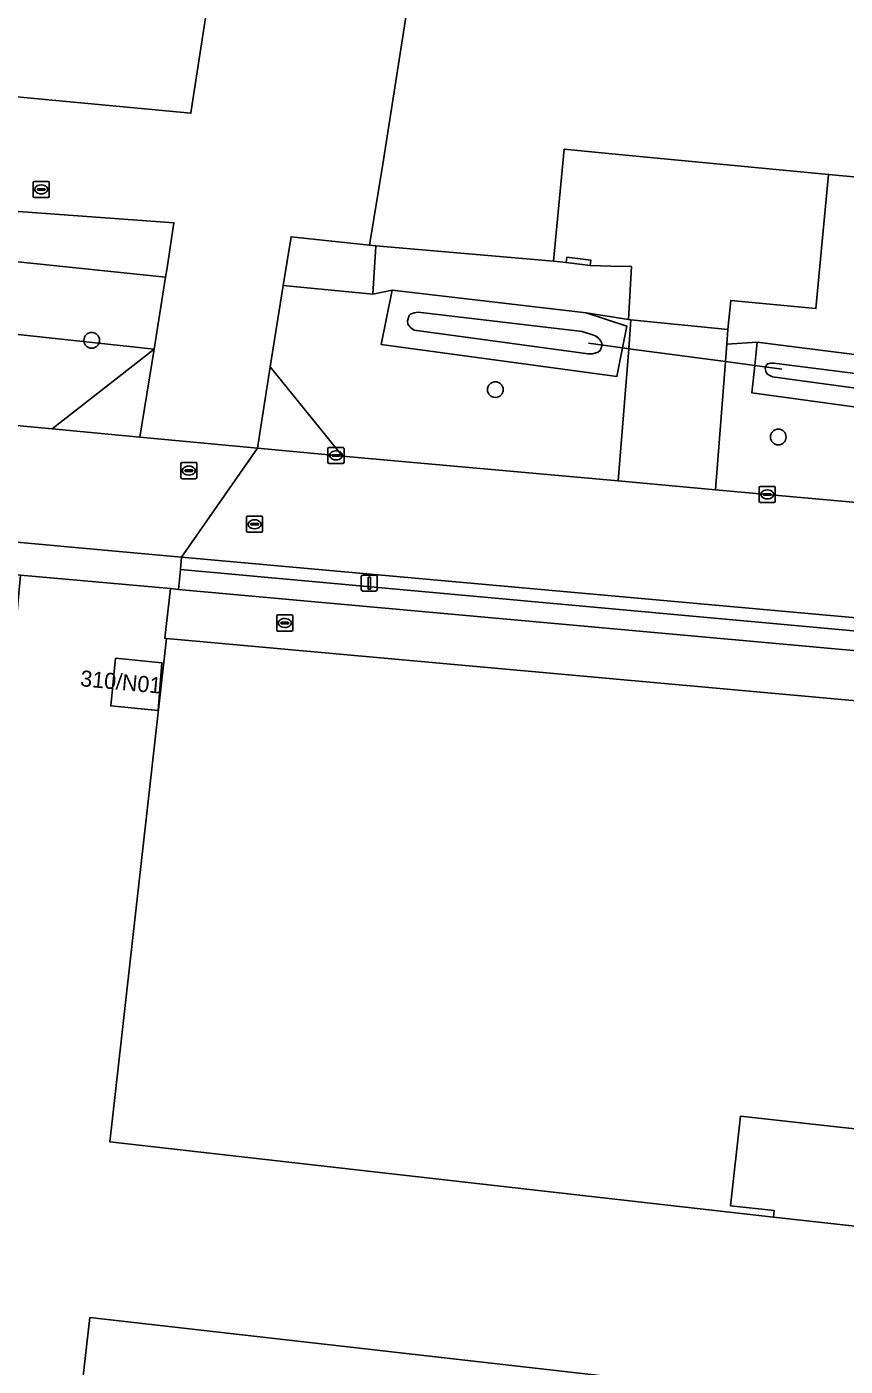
# Model space of a CAD drawing. Extents: x 161385 to 162589, y 388479 to 389756.
# Drawn here: x 162279.1 to 162330.1, y 388809.1 to 388892.6 of the extents above; entities that cross this region are included whole.
import ezdxf

# ---------------------------------------------------------------- set-up
doc = ezdxf.new("R2010")
doc.units = 0
for name, color, linetype in [('IMGEO_Berm_groen', 7, 'Continuous'), ('IMGEO_Boom', 7, 'Continuous'), ('IMGEO_Duiker', 7, 'Continuous'), ('IMGEO_Erf', 7, 'Continuous'), ('IMGEO_Groenvoorziening', 7, 'Continuous'), ('IMGEO_Haag', 7, 'Continuous'), ('IMGEO_Kolk', 7, 'Continuous'), ('IMGEO_Lichtmast', 7, 'Continuous'), ('IMGEO_Oever', 7, 'Continuous'), ('IMGEO_Pand', 7, 'Continuous'), ('IMGEO_Pand_nummerreeks', 7, 'Continuous'), ('IMGEO_Pand_overbouw', 7, 'Continuous'), ('IMGEO_Parkeervlak_open', 7, 'Continuous'), ('IMGEO_Rijbaan_lokaal_gesloten', 7, 'Continuous'), ('IMGEO_Rioolput', 7, 'Continuous'), ('IMGEO_Voetpad_open', 7, 'Continuous'), ('IMGEO_Waterloop', 7, 'Continuous')]:
    doc.layers.add(name, color=color, linetype=linetype)

msp = doc.modelspace()

# ---------------------------------------------------------------- linework, layer by layer
at = {"layer": 'IMGEO_Berm_groen'}
msp.add_lwpolyline([(162288.732, 388859.544), (162288.662, 388858.772), (162339.281, 388854.162), (162339.344, 388854.997)], close=True, dxfattribs=at)
at = {"layer": 'IMGEO_Boom'}
for centre in [(162283.136, 388873.045), (162308.29, 388869.973), (162325.926, 388867.021)]:
    msp.add_circle(centre, 0.489, dxfattribs=at)
at = {"layer": 'IMGEO_Duiker'}
msp.add_lwpolyline([(162314.103, 388872.857), (162316.222, 388872.573), (162316.604, 388872.522), (162322.632, 388871.715), (162324.463, 388871.47), (162326.14, 388871.245)], dxfattribs=at)
at = {"layer": 'IMGEO_Erf'}
for points in [[(162301.186, 388963.969), (162289.317, 388887.215), (162289.314, 388887.191), (162277.129, 388888.332), (162269.619, 388894.999)], [(162260.733, 388892.727), (162265.464, 388888.449), (162265.979, 388889.025), (162274.193, 388881.455), (162274.374, 388883.406), (162276.174, 388883.247), (162275.984, 388881.265), (162288.259, 388880.37), (162287.835, 388877.552), (162287.741, 388876.97), (162287.02, 388872.502), (162286.134, 388867.013), (162293.465, 388866.329), (162294.266, 388871.396), (162295.067, 388876.463), (162295.565, 388879.495), (162300.445, 388878.969), (162301.281, 388884.015), (162311.401, 388948.624)], [(162336.306, 388823.293), (162323.575, 388824.702), (162322.952, 388819.118), (162325.666, 388818.823), (162325.623, 388818.422), (162284.27, 388823.103), (162287.807, 388854.476), (162287.687, 388854.487), (162288.036, 388857.574), (162278.689, 388858.42), (162278.404, 388855.258), (162275.28, 388820.598), (162223.371, 388826.41), (162220.139, 388826.772), (162222.783, 388816.053), (162224.711, 388808.14)], [(162331.623, 388785.008), (162280.589, 388790.807), (162283.02, 388812.167), (162334.332, 388806.326)]]:
    msp.add_lwpolyline(points, dxfattribs=at)
msp.add_lwpolyline([(162287.271, 388849.977), (162284.326, 388850.264), (162284.615, 388853.236), (162287.513, 388852.954)], close=True, dxfattribs=at)
at = {"layer": 'IMGEO_Groenvoorziening'}
for points in [[(162246.366, 388906.419), (162244.168, 388904.202), (162253.513, 388895.632), (162268.907, 388882.41), (162271.544, 388879.695), (162274.103, 388878.687), (162276.507, 388878.144), (162287.741, 388876.97), (162287.835, 388877.552), (162288.259, 388880.37), (162275.984, 388881.265), (162274.193, 388881.455), (162265.979, 388889.025), (162265.464, 388888.449), (162260.733, 388892.727), (162261.179, 388893.207)], [(162244.168, 388904.202), (162245.865, 388891.335), (162245.122, 388884.323), (162255.956, 388878.959), (162267.356, 388874.616), (162287.02, 388872.502), (162287.741, 388876.97), (162276.507, 388878.144), (162274.103, 388878.687), (162271.544, 388879.695), (162268.907, 388882.41), (162253.513, 388895.632)], [(162255.956, 388878.959), (162245.122, 388884.323), (162242.339, 388884.577), (162241.028, 388871.088), (162277.557, 388867.813), (162280.677, 388867.522), (162287.02, 388872.502), (162267.356, 388874.616)], [(162300.445, 388878.969), (162295.565, 388879.495), (162295.067, 388876.463), (162300.649, 388875.922), (162300.833, 388878.935)], [(162316.778, 388877.634), (162315.492, 388877.672), (162314.206, 388877.71), (162312.713, 388877.887), (162311.923, 388877.971), (162300.833, 388878.935), (162300.649, 388875.922), (162301.863, 388876.172), (162313.948, 388874.754), (162316.588, 388874.337)], [(162316.604, 388872.522), (162316.746, 388874.312), (162316.588, 388874.337), (162313.948, 388874.754), (162316.487, 388873.93), (162316.222, 388872.573), (162315.873, 388870.781), (162301.185, 388872.774), (162301.863, 388876.172), (162300.649, 388875.922), (162295.067, 388876.463), (162294.266, 388871.396), (162298.769, 388865.835), (162315.95, 388864.281)]]:
    msp.add_lwpolyline(points, close=True, dxfattribs=at)
for points in [[(162357.822, 388901.413), (162352.295, 388877.281), (162351.615, 388874.313), (162351.606, 388874.213), (162348.394, 388874.517), (162334.421, 388875.837), (162335.09, 388882.809), (162329.062, 388883.383), (162328.267, 388875.021), (162322.959, 388875.526), (162322.786, 388873.71), (162322.717, 388872.815), (162324.614, 388872.923), (162339.222, 388871.074), (162341.408, 388871.373), (162344.443, 388871.418)], [(162344.503, 388866.742), (162340.703, 388867.092), (162339.127, 388867.743), (162324.286, 388869.767), (162324.463, 388871.47), (162324.614, 388872.923), (162322.717, 388872.815), (162322.632, 388871.715), (162322.016, 388863.733), (162325.24, 388863.441), (162339.626, 388862.148), (162340.13, 388862.129), (162341.25, 388862.022), (162342.375, 388862.016), (162343.496, 388862.11), (162344.605, 388862.304), (162345.691, 388862.596), (162346.747, 388862.984), (162345.812, 388867.043)], [(162339.12, 388852.95), (162288.552, 388857.528), (162288.036, 388857.574), (162287.687, 388854.487), (162287.807, 388854.476), (162339.069, 388849.833)]]:
    msp.add_lwpolyline(points, dxfattribs=at)
at = {"layer": 'IMGEO_Haag'}
msp.add_lwpolyline([(162300.445, 388878.969), (162295.565, 388879.495), (162295.067, 388876.463), (162300.649, 388875.922), (162300.833, 388878.935)], close=True, dxfattribs=at)
at = {"layer": 'IMGEO_Kolk'}
for p, q in [((162297.859, 388865.447), (162297.859, 388866.299)), ((162297.934, 388866.373), (162298.786, 388866.373)), ((162298.118, 388865.867), (162298.118, 388865.879)), ((162298.556, 388865.83), (162298.158, 388865.83)), ((162298.161, 388865.916), (162298.559, 388865.916)), ((162298.347, 388866.153), (162298.372, 388866.153)), ((162298.602, 388865.879), (162298.602, 388865.867)), ((162298.86, 388866.299), (162298.86, 388865.447)), ((162298.786, 388865.373), (162297.934, 388865.373)), ((162298.37, 388865.593), (162298.345, 388865.593)), ((162324.739, 388863.017), (162324.739, 388863.869)), ((162324.814, 388863.943), (162325.666, 388863.943)), ((162324.998, 388863.437), (162324.998, 388863.449)), ((162325.436, 388863.4), (162325.038, 388863.4)), ((162325.041, 388863.486), (162325.439, 388863.486)), ((162325.227, 388863.723), (162325.252, 388863.723)), ((162325.482, 388863.449), (162325.482, 388863.437)), ((162325.74, 388863.869), (162325.74, 388863.017)), ((162325.666, 388862.943), (162324.814, 388862.943)), ((162325.25, 388863.163), (162325.225, 388863.163))]:
    msp.add_line(p, q, dxfattribs=at)
for points in [[(162297.859, 388865.447), (162297.859, 388866.299)], [(162297.934, 388866.373), (162298.786, 388866.373)], [(162298.86, 388866.299), (162298.86, 388865.447)], [(162298.786, 388865.373), (162297.934, 388865.373)], [(162324.739, 388863.017), (162324.739, 388863.869)], [(162324.814, 388863.943), (162325.666, 388863.943)], [(162325.74, 388863.869), (162325.74, 388863.017)], [(162325.666, 388862.943), (162324.814, 388862.943)]]:
    msp.add_lwpolyline(points, dxfattribs=at)
for centre, radius, start, end in [((162297.936, 388866.297), 0.0765, 91.55205, 178.44795), ((162297.936, 388866.297), 0.0765, 91.55205, 178.44795), ((162298.158, 388865.876), 0.0403, 85.87752, 175.75265), ((162298.155, 388865.866), 0.0366, 178.93798, 274.71019), ((162298.559, 388865.873), 0.043, 264.86636, 352.45326), ((162298.563, 388865.878), 0.0386, 1.73085, 96.63898), ((162298.784, 388866.297), 0.0765, 1.55205, 88.44795), ((162298.784, 388866.297), 0.0765, 1.55205, 88.44795), ((162297.936, 388865.449), 0.0765, 181.55205, 268.44795), ((162297.936, 388865.449), 0.0765, 181.55205, 268.44795), ((162298.784, 388865.449), 0.0765, 271.55205, 358.44795), ((162298.784, 388865.449), 0.0765, 271.55205, 358.44795), ((162324.816, 388863.867), 0.0765, 91.55205, 178.44795), ((162324.816, 388863.867), 0.0765, 91.55205, 178.44795), ((162325.038, 388863.446), 0.0403, 85.87752, 175.75265), ((162325.035, 388863.436), 0.0366, 178.93798, 274.71019), ((162325.439, 388863.443), 0.043, 264.86636, 352.45326), ((162325.443, 388863.448), 0.0386, 1.73085, 96.63898), ((162325.664, 388863.867), 0.0765, 1.55205, 88.44795), ((162325.664, 388863.867), 0.0765, 1.55205, 88.44795), ((162324.816, 388863.019), 0.0765, 181.55205, 268.44795), ((162324.816, 388863.019), 0.0765, 181.55205, 268.44795), ((162325.664, 388863.019), 0.0765, 271.55205, 358.44795), ((162325.664, 388863.019), 0.0765, 271.55205, 358.44795)]:
    msp.add_arc(centre, radius, start, end, dxfattribs=at)
for centre, major_axis, ratio, start_param, end_param in [((162298.346, 388865.873), (-0.387, 0.002), 0.722429, 4.712389, 7.853982), ((162298.371, 388865.873), (-0.39, 0.002), 0.717154, 1.570796, 4.712389), ((162325.226, 388863.443), (-0.387, 0.002), 0.722429, 4.712389, 7.853982), ((162325.251, 388863.443), (-0.39, 0.002), 0.717154, 1.570796, 4.712389)]:
    msp.add_ellipse(centre, major_axis=major_axis, ratio=ratio, start_param=start_param, end_param=end_param, dxfattribs=at)
at = {"layer": 'IMGEO_Lichtmast'}
for p, q in [((162299.936, 388857.522), (162299.936, 388858.322)), ((162299.936, 388858.322), (162299.936, 388857.522)), ((162300.036, 388858.422), (162300.826, 388858.422)), ((162300.826, 388858.422), (162300.036, 388858.422)), ((162300.926, 388858.322), (162300.926, 388857.522)), ((162300.926, 388857.522), (162300.926, 388858.322)), ((162300.826, 388857.422), (162300.036, 388857.422)), ((162300.036, 388857.422), (162300.826, 388857.422))]:
    msp.add_line(p, q, dxfattribs=at)
msp.add_lwpolyline([(162300.356, 388858.297), (162300.506, 388858.297), (162300.506, 388857.547), (162300.356, 388857.547), (162300.356, 388858.297)], dxfattribs=at)
for centre, start, end in [((162300.036, 388858.322), 90, 180), ((162300.036, 388858.322), 90, 180), ((162300.826, 388858.322), 0, 90), ((162300.826, 388858.322), 360, 90), ((162300.036, 388857.522), 180, 270), ((162300.036, 388857.522), 180, 270), ((162300.826, 388857.522), 270, 0), ((162300.826, 388857.522), 270, 0)]:
    msp.add_arc(centre, 0.1, start, end, dxfattribs=at)
at = {"layer": 'IMGEO_Oever'}
for points in [[(162316.487, 388873.93), (162313.948, 388874.754), (162301.863, 388876.172), (162301.185, 388872.774), (162315.873, 388870.781), (162316.222, 388872.573)], [(162303.226, 388873.679), (162303.021, 388873.826), (162302.846, 388874.053), (162302.809, 388874.249), (162302.919, 388874.601), (162303.005, 388874.677), (162303.228, 388874.763), (162303.49, 388874.802), (162313.697, 388873.604), (162314.534, 388873.332), (162314.757, 388873.135), (162314.913, 388872.92), (162314.944, 388872.744), (162314.822, 388872.414), (162314.705, 388872.298), (162314.353, 388872.197), (162314.068, 388872.208)]]:
    msp.add_lwpolyline(points, close=True, dxfattribs=at)
for points in [[(162344.443, 388871.418), (162341.408, 388871.373), (162339.222, 388871.074), (162324.614, 388872.923), (162324.463, 388871.47), (162324.286, 388869.767), (162339.127, 388867.743), (162340.703, 388867.092), (162344.503, 388866.742)], [(162325.561, 388870.768), (162325.389, 388870.843), (162325.243, 388870.943), (162325.175, 388871.03), (162325.117, 388871.285), (162325.192, 388871.512), (162325.275, 388871.574), (162325.447, 388871.614), (162325.649, 388871.618), (162339.228, 388869.9), (162341.496, 388870.21), (162344.685, 388870.255)], [(162344.776, 388867.889), (162344.6, 388867.902), (162340.985, 388868.235), (162339.433, 388868.876), (162325.561, 388870.768)]]:
    msp.add_lwpolyline(points, dxfattribs=at)
at = {"layer": 'IMGEO_Pand'}
for points in [[(162264.946, 388889.847), (162268.212, 388893.373), (162269.619, 388894.999), (162277.129, 388888.332), (162289.314, 388887.191), (162289.317, 388887.215), (162301.186, 388963.969), (162272.023, 388970.049), (162248.708, 388913.782), (162251.019, 388911.636), (162246.366, 388906.419), (162261.179, 388893.207)], [(162329.062, 388883.383), (162335.09, 388882.809), (162334.421, 388875.837), (162348.394, 388874.517), (162351.606, 388874.213), (162351.615, 388874.313), (162352.295, 388877.281), (162357.822, 388901.413), (162350.993, 388902.975), (162351.799, 388906.466), (162359.012, 388937.762), (162358.244, 388937.938), (162354.138, 388938.878), (162348.019, 388940.254), (162347.32, 388937.213), (162321.535, 388943.142), (162322.217, 388946.171), (162311.401, 388948.624), (162301.281, 388884.015), (162300.445, 388878.969), (162300.833, 388878.935), (162311.923, 388877.971), (162312.587, 388884.951), (162316.198, 388884.607)], [(162312.713, 388877.887), (162314.206, 388877.71), (162314.244, 388878.037), (162312.752, 388878.215)], [(162287.513, 388852.954), (162284.615, 388853.236), (162284.326, 388850.264), (162287.271, 388849.977)], [(162334.332, 388806.326), (162283.02, 388812.167), (162280.589, 388790.807), (162331.623, 388785.008), (162331.535, 388784.179), (162331.85, 388784.151), (162332.058, 388785.932), (162334.379, 388785.658), (162334.24, 388784.715), (162338.936, 388784.171), (162340.623, 388800.353), (162340.638, 388800.493), (162333.756, 388801.193), (162334.321, 388806.194)]]:
    msp.add_lwpolyline(points, close=True, dxfattribs=at)
msp.add_lwpolyline([(162339.069, 388849.833), (162287.807, 388854.476), (162284.27, 388823.103), (162325.623, 388818.422), (162325.666, 388818.823), (162322.952, 388819.118), (162323.575, 388824.702), (162336.306, 388823.293), (162336.398, 388824.261), (162341.857, 388823.664), (162342.013, 388824.299), (162342.869, 388824.995), (162343.228, 388825.075), (162343.546, 388825.042), (162343.766, 388826.99), (162345.439, 388841.767)], dxfattribs=at)
at = {"layer": 'IMGEO_Pand_overbouw'}
msp.add_lwpolyline([(162336.306, 388823.293), (162323.575, 388824.702), (162322.952, 388819.118), (162325.666, 388818.823), (162325.623, 388818.422), (162335.604, 388817.317)], close=True, dxfattribs=at)
at = {"layer": 'IMGEO_Parkeervlak_open'}
msp.add_lwpolyline([(162316.588, 388874.337), (162316.746, 388874.312), (162322.786, 388873.71), (162322.959, 388875.526), (162328.267, 388875.021), (162329.062, 388883.383), (162316.198, 388884.607), (162312.587, 388884.951), (162311.923, 388877.971), (162312.713, 388877.887), (162312.752, 388878.215), (162314.244, 388878.037), (162314.206, 388877.71), (162315.492, 388877.672), (162316.778, 388877.634)], close=True, dxfattribs=at)
at = {"layer": 'IMGEO_Rijbaan_lokaal_gesloten'}
for points in [[(162224.271, 388865.333), (162239.911, 388863.928), (162253.792, 388862.682), (162273.651, 388860.898), (162288.732, 388859.544), (162293.465, 388866.329), (162286.134, 388867.013), (162280.677, 388867.522), (162277.557, 388867.813), (162241.028, 388871.088), (162237.058, 388871.444), (162235.953, 388871.543), (162215.116, 388873.448)], [(162339.626, 388862.148), (162325.24, 388863.441), (162322.016, 388863.733), (162315.95, 388864.281), (162298.769, 388865.835), (162298.36, 388865.872), (162293.465, 388866.329), (162288.732, 388859.544), (162339.344, 388854.997)]]:
    msp.add_lwpolyline(points, dxfattribs=at)
at = {"layer": 'IMGEO_Rioolput'}
for p, q in [((162279.489, 388882.022), (162279.489, 388882.874)), ((162279.564, 388882.948), (162280.416, 388882.948)), ((162279.748, 388882.442), (162279.748, 388882.454)), ((162280.186, 388882.405), (162279.788, 388882.405)), ((162279.791, 388882.491), (162280.189, 388882.491)), ((162279.977, 388882.728), (162280.002, 388882.728)), ((162280.232, 388882.454), (162280.232, 388882.442)), ((162280.49, 388882.874), (162280.49, 388882.022)), ((162280.416, 388881.948), (162279.564, 388881.948)), ((162280, 388882.168), (162279.975, 388882.168)), ((162288.69, 388864.499), (162288.69, 388865.351)), ((162288.765, 388865.425), (162289.617, 388865.425)), ((162288.949, 388864.919), (162288.949, 388864.931)), ((162289.387, 388864.882), (162288.989, 388864.882)), ((162288.992, 388864.968), (162289.39, 388864.968)), ((162289.178, 388865.205), (162289.203, 388865.205)), ((162289.433, 388864.931), (162289.433, 388864.919)), ((162289.691, 388865.351), (162289.691, 388864.499)), ((162289.617, 388864.425), (162288.765, 388864.425)), ((162289.201, 388864.645), (162289.176, 388864.645)), ((162292.787, 388861.16), (162292.787, 388862.012)), ((162292.862, 388862.086), (162293.714, 388862.086)), ((162293.046, 388861.58), (162293.046, 388861.592)), ((162293.484, 388861.543), (162293.086, 388861.543)), ((162293.089, 388861.629), (162293.487, 388861.629)), ((162293.275, 388861.866), (162293.3, 388861.866)), ((162293.53, 388861.592), (162293.53, 388861.58)), ((162293.788, 388862.012), (162293.788, 388861.16)), ((162293.714, 388861.086), (162292.862, 388861.086)), ((162293.298, 388861.306), (162293.273, 388861.306)), ((162294.67, 388855.007), (162294.67, 388855.859)), ((162294.745, 388855.933), (162295.597, 388855.933)), ((162295.158, 388855.713), (162295.183, 388855.713)), ((162295.671, 388855.859), (162295.671, 388855.007)), ((162295.597, 388854.933), (162294.745, 388854.933)), ((162294.929, 388855.427), (162294.929, 388855.439)), ((162295.367, 388855.39), (162294.969, 388855.39)), ((162294.972, 388855.476), (162295.37, 388855.476)), ((162295.181, 388855.153), (162295.156, 388855.153)), ((162295.413, 388855.439), (162295.413, 388855.427))]:
    msp.add_line(p, q, dxfattribs=at)
for points in [[(162279.489, 388882.022), (162279.489, 388882.874)], [(162279.564, 388882.948), (162280.416, 388882.948)], [(162280.49, 388882.874), (162280.49, 388882.022)], [(162280.416, 388881.948), (162279.564, 388881.948)], [(162288.69, 388864.499), (162288.69, 388865.351)], [(162288.765, 388865.425), (162289.617, 388865.425)], [(162289.691, 388865.351), (162289.691, 388864.499)], [(162289.617, 388864.425), (162288.765, 388864.425)], [(162292.787, 388861.16), (162292.787, 388862.012)], [(162292.862, 388862.086), (162293.714, 388862.086)], [(162293.788, 388862.012), (162293.788, 388861.16)], [(162293.714, 388861.086), (162292.862, 388861.086)], [(162294.67, 388855.007), (162294.67, 388855.859)], [(162294.745, 388855.933), (162295.597, 388855.933)], [(162295.671, 388855.859), (162295.671, 388855.007)], [(162295.597, 388854.933), (162294.745, 388854.933)]]:
    msp.add_lwpolyline(points, dxfattribs=at)
for centre, radius, start, end in [((162279.566, 388882.872), 0.0765, 91.55205, 178.44795), ((162279.566, 388882.872), 0.0765, 91.55205, 178.44795), ((162279.788, 388882.451), 0.0403, 85.87752, 175.75265), ((162279.785, 388882.441), 0.0366, 178.93798, 274.71019), ((162280.189, 388882.448), 0.043, 264.86636, 352.45326), ((162280.193, 388882.453), 0.0386, 1.73085, 96.63898), ((162280.414, 388882.872), 0.0765, 1.55205, 88.44795), ((162280.414, 388882.872), 0.0765, 1.55205, 88.44795), ((162279.566, 388882.024), 0.0765, 181.55205, 268.44795), ((162279.566, 388882.024), 0.0765, 181.55205, 268.44795), ((162280.414, 388882.024), 0.0765, 271.55205, 358.44795), ((162280.414, 388882.024), 0.0765, 271.55205, 358.44795), ((162288.767, 388865.349), 0.0765, 91.55205, 178.44795), ((162288.767, 388865.349), 0.0765, 91.55205, 178.44795), ((162288.989, 388864.928), 0.0403, 85.87752, 175.75265), ((162288.986, 388864.918), 0.0366, 178.93798, 274.71019), ((162289.39, 388864.925), 0.043, 264.86636, 352.45326), ((162289.394, 388864.93), 0.0386, 1.73085, 96.63898), ((162289.615, 388865.349), 0.0765, 1.55205, 88.44795), ((162289.615, 388865.349), 0.0765, 1.55205, 88.44795), ((162288.767, 388864.501), 0.0765, 181.55205, 268.44795), ((162288.767, 388864.501), 0.0765, 181.55205, 268.44795), ((162289.615, 388864.501), 0.0765, 271.55205, 358.44795), ((162289.615, 388864.501), 0.0765, 271.55205, 358.44795), ((162292.864, 388862.01), 0.0765, 91.55205, 178.44795), ((162292.864, 388862.01), 0.0765, 91.55205, 178.44795), ((162293.086, 388861.589), 0.0403, 85.87752, 175.75265), ((162293.083, 388861.579), 0.0366, 178.93798, 274.71019), ((162293.487, 388861.586), 0.043, 264.86636, 352.45326), ((162293.491, 388861.591), 0.0386, 1.73085, 96.63898), ((162293.712, 388862.01), 0.0765, 1.55205, 88.44795), ((162293.712, 388862.01), 0.0765, 1.55205, 88.44795), ((162292.864, 388861.162), 0.0765, 181.55205, 268.44795), ((162292.864, 388861.162), 0.0765, 181.55205, 268.44795), ((162293.712, 388861.162), 0.0765, 271.55205, 358.44795), ((162293.712, 388861.162), 0.0765, 271.55205, 358.44795), ((162294.747, 388855.857), 0.0765, 91.55205, 178.44795), ((162294.747, 388855.857), 0.0765, 91.55205, 178.44795), ((162295.595, 388855.857), 0.0765, 1.55205, 88.44795), ((162295.595, 388855.857), 0.0765, 1.55205, 88.44795), ((162294.747, 388855.009), 0.0765, 181.55205, 268.44795), ((162294.747, 388855.009), 0.0765, 181.55205, 268.44795), ((162294.969, 388855.436), 0.0403, 85.87752, 175.75265), ((162294.966, 388855.426), 0.0366, 178.93798, 274.71019), ((162295.37, 388855.433), 0.043, 264.86636, 352.45326), ((162295.374, 388855.438), 0.0386, 1.73085, 96.63898), ((162295.595, 388855.009), 0.0765, 271.55205, 358.44795), ((162295.595, 388855.009), 0.0765, 271.55205, 358.44795)]:
    msp.add_arc(centre, radius, start, end, dxfattribs=at)
for centre, major_axis, ratio, start_param, end_param in [((162279.976, 388882.448), (-0.387, 0.002), 0.722429, 4.712389, 7.853982), ((162280.001, 388882.448), (-0.39, 0.002), 0.717154, 1.570796, 4.712389), ((162289.177, 388864.925), (-0.387, 0.002), 0.722429, 4.712389, 7.853982), ((162289.202, 388864.925), (-0.39, 0.002), 0.717154, 1.570796, 4.712389), ((162293.274, 388861.586), (-0.387, 0.002), 0.722429, 4.712389, 7.853982), ((162293.299, 388861.586), (-0.39, 0.002), 0.717154, 1.570796, 4.712389), ((162295.157, 388855.433), (-0.387, 0.002), 0.722429, 4.712389, 7.853982), ((162295.182, 388855.433), (-0.39, 0.002), 0.717154, 1.570796, 4.712389)]:
    msp.add_ellipse(centre, major_axis=major_axis, ratio=ratio, start_param=start_param, end_param=end_param, dxfattribs=at)
at = {"layer": 'IMGEO_Voetpad_open'}
for points in [[(162322.717, 388872.815), (162322.786, 388873.71), (162316.746, 388874.312), (162316.604, 388872.522), (162315.95, 388864.281), (162322.016, 388863.733), (162322.632, 388871.715)], [(162287.02, 388872.502), (162280.677, 388867.522), (162286.134, 388867.013)], [(162294.266, 388871.396), (162293.465, 388866.329), (162298.36, 388865.872), (162298.769, 388865.835)], [(162288.036, 388857.574), (162288.552, 388857.528), (162288.662, 388858.772), (162288.732, 388859.544), (162273.651, 388860.898), (162273.641, 388860.106), (162273.523, 388858.888), (162278.689, 388858.42)], [(162288.662, 388858.772), (162288.552, 388857.528), (162339.12, 388852.95), (162339.281, 388854.162)]]:
    msp.add_lwpolyline(points, close=True, dxfattribs=at)
at = {"layer": 'IMGEO_Waterloop'}
msp.add_lwpolyline([(162303.49, 388874.802), (162303.228, 388874.763), (162303.005, 388874.677), (162302.919, 388874.601), (162302.809, 388874.249), (162302.846, 388874.053), (162303.021, 388873.826), (162303.226, 388873.679), (162314.068, 388872.208), (162314.353, 388872.197), (162314.705, 388872.298), (162314.822, 388872.414), (162314.944, 388872.744), (162314.913, 388872.92), (162314.757, 388873.135), (162314.534, 388873.332), (162313.697, 388873.604)], close=True, dxfattribs=at)
for points in [[(162325.649, 388871.618), (162325.447, 388871.614), (162325.275, 388871.574), (162325.192, 388871.512), (162325.117, 388871.285), (162325.175, 388871.03), (162325.243, 388870.943), (162325.389, 388870.843), (162325.561, 388870.768), (162339.433, 388868.876), (162340.985, 388868.235), (162344.6, 388867.902), (162344.776, 388867.889)], [(162344.685, 388870.255), (162341.496, 388870.21), (162339.228, 388869.9), (162325.649, 388871.618)]]:
    msp.add_lwpolyline(points, dxfattribs=at)

# ---------------------------------------------------------------- texts
at = {"layer": 'IMGEO_Pand_nummerreeks'}
msp.add_text('310/N01', height=1, rotation=354.67725, dxfattribs=at).set_placement((162282.392, 388851.5))

doc.saveas('drawing.dxf')
